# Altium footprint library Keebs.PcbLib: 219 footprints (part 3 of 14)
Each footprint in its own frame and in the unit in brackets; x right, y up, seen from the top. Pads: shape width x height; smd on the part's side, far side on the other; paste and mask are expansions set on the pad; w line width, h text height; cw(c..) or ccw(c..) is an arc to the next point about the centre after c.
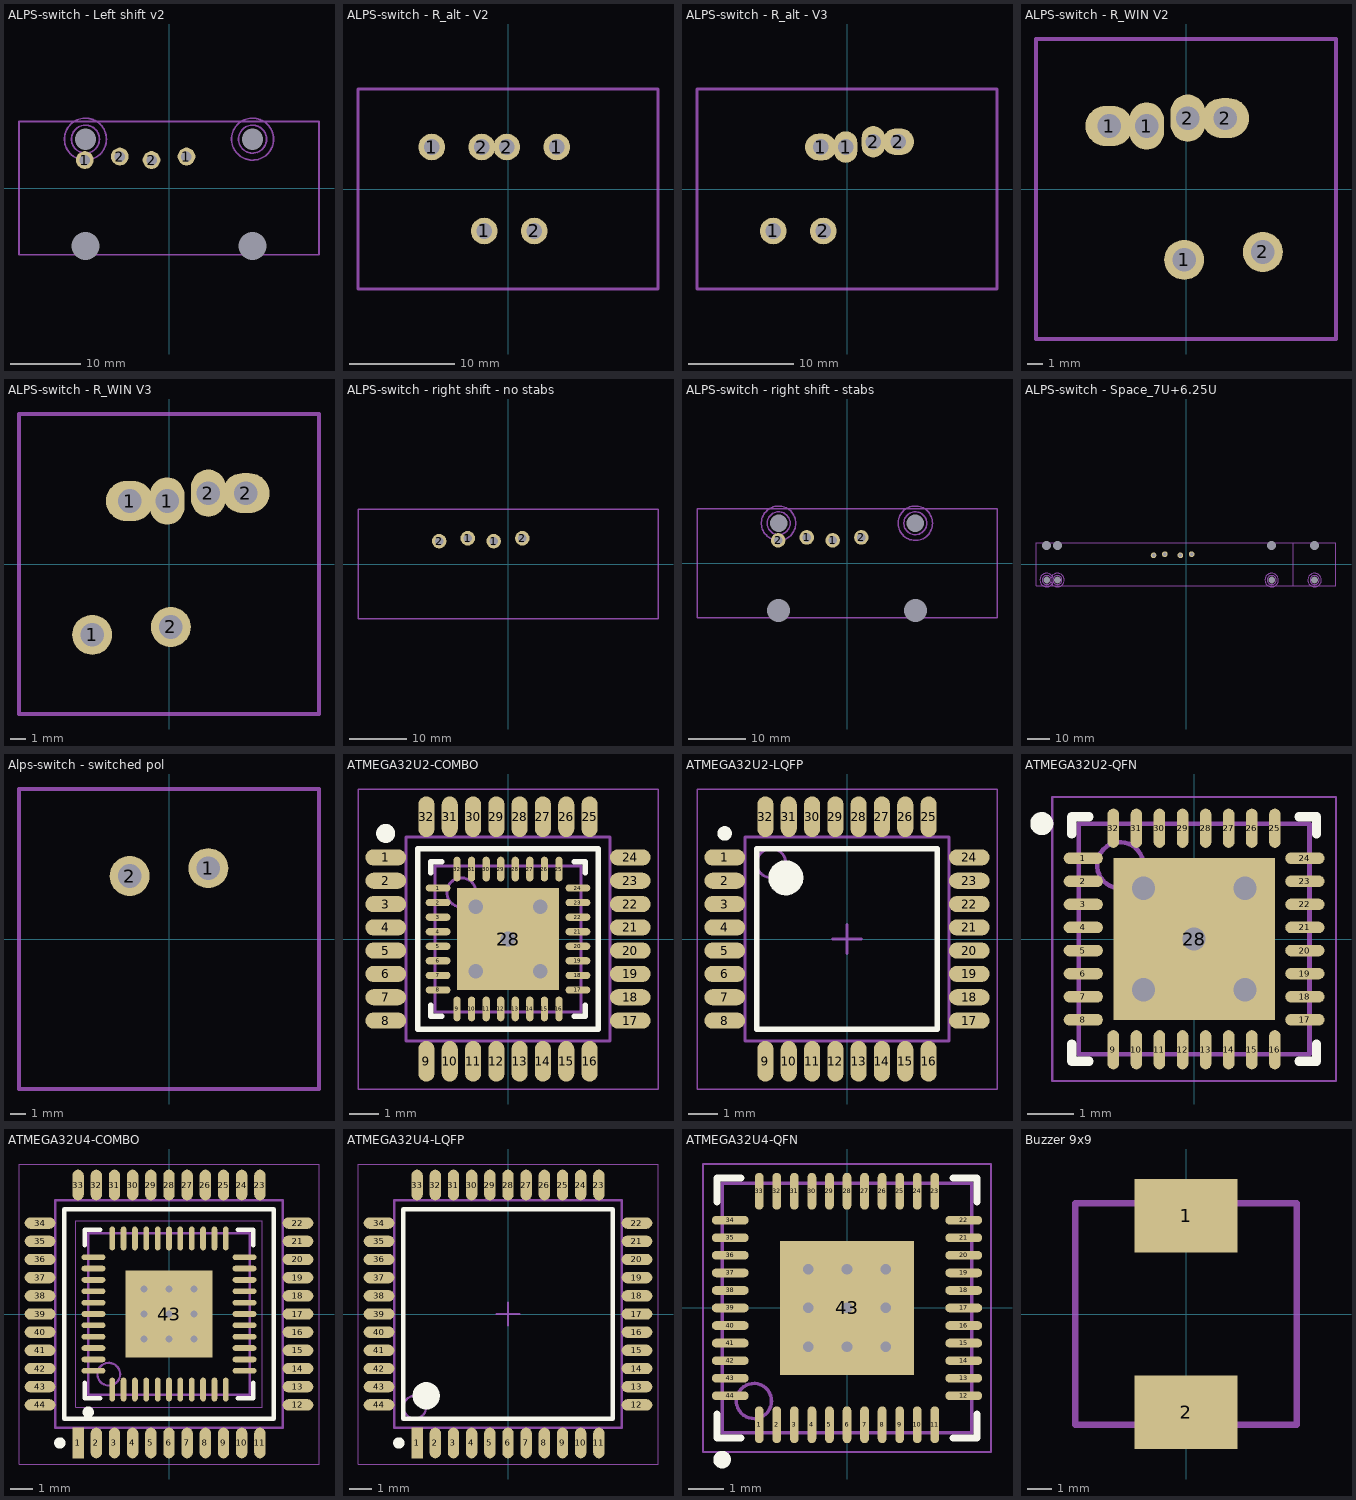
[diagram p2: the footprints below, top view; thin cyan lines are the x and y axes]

## ALPS-switch - Left shift v2 [mm]
pads (10):
  round 2.54 hole 1.5 mask-0.5: 1(-12.025,4) 1(2.5,4.5) 2(-7.025,4.5) 2(-2.5,4)
  round 1.524 hole 4 unplated: ""(-11.938,-8.255) ""(11.938,-8.255)
  round 1.524 hole 3.048 unplated: ""(-11.938,6.985) ""(11.938,6.985)
  round 1 on Mech13: ""(-9.525,0) ""(0,0)
Mechanical 13:
  lines w0.254: -21.431,-9.525 21.431,-9.525 21.431,9.525 -21.431,9.525 -21.431,-9.525
  text ".Designator" at -5.45,-3.925 h0.7
Mechanical 15:
  circle w0.254: c11.938,6.985 r2
  circle w0.254: c11.938,6.985 r3
  circle w0.254: c-11.938,6.985 r2
  circle w0.254: c-11.938,6.985 r3

## ALPS-switch - R_alt - V2 [mm]
pads (9):
  round 2.54 hole 1.5 mask-0.5: 1(-7.263,4) 1(-2.262,-4) 1(4.644,4) 2(-2.5,4) 2(-0.119,4) 2(2.5,-4)
  round 1 on Mech13: ""(-4.763,0) ""(0,0) ""(2.381,0)
Mechanical 13:
  lines w0.254: -14.287,-9.525 -14.287,9.525 14.287,9.525 14.287,-9.525 -14.287,-9.525
  text ".Designator" at -10.775,-6.175 h0.7

## ALPS-switch - R_alt - V3 [mm]
pads (9):
  round 2.54 hole 1.5 mask-0.5: 1(-7.025,-4) 2(-2.262,-4)
  oval 3x2.54 hole 1.5 mask-0.7: 1(-2.5,4) 2(4.881,4.5)
  oval 2.2x3 hole 1.5 mask-0.7: 1(-0.119,4) 2(2.5,4.5)
  round 1 on Mech13: ""(-4.763,0) ""(0,0) ""(2.381,0)
Mechanical 13:
  lines w0.254: -14.287,-9.525 -14.287,9.525 14.287,9.525 14.287,-9.525 -14.287,-9.525
  text ".Designator" at -10.775,-6.175 h0.7

## ALPS-switch - R_WIN V2 [mm]
pads (9):
  oval 3x2.54 hole 1.5 mask-0.7: 1(-4.881,4) 2(2.5,4.5)
  oval 2.2x3 hole 1.5 mask-0.7: 1(-2.5,4) 2(0.119,4.5)
  round 2.54 hole 1.5 mask-0.5: 1(-0.119,-4.5) 2(4.881,-4)
  round 1 on Mech13: ""(-2.381,0) ""(0,0) ""(2.381,0)
Mechanical 13:
  lines w0.254: -9.525,-9.525 9.525,-9.525 9.525,9.525 -9.525,9.525 -9.525,-9.525
  text ".Designator" at -4.225,-8.325 h0.7

## ALPS-switch - R_WIN V3 [mm]
pads (9):
  round 2.54 hole 1.5 mask-0.5: 1(-4.881,-4.5) 2(0.119,-4)
  oval 3x2.54 hole 1.5 mask-0.7: 1(-2.5,4) 2(4.881,4.5)
  oval 2.2x3 hole 1.5 mask-0.7: 1(-0.119,4) 2(2.5,4.5)
  round 1 on Mech13: ""(-2.381,0) ""(0,0) ""(2.381,0)
Mechanical 13:
  lines w0.254: -9.525,-9.525 -9.525,9.525 9.525,9.525 9.525,-9.525 -9.525,-9.525
  text ".Designator" at -4.225,-8.325 h0.7

## ALPS-switch - right shift - no stabs [mm]
pads (6):
  round 2.54 hole 1.5 mask-0.5: 1(-7.025,4.5) 1(-2.5,4) 2(-12.025,4) 2(2.5,4.5)
  round 1 on Mech13: ""(-9.525,0) ""(0,0)
Mechanical 13:
  lines w0.254: -26.194,-9.525 26.194,-9.525 26.194,9.525 -26.194,9.525 -26.194,-9.525
  text ".Designator" at -4.3,-5.55 h0.7

## ALPS-switch - right shift - stabs [mm]
pads (10):
  round 2.54 hole 1.5 mask-0.5: 1(-7.025,4.5) 1(-2.5,4) 2(-12.025,4) 2(2.5,4.5)
  round 1.524 hole 4 unplated: ""(-11.938,-8.255) ""(11.938,-8.255)
  round 1.524 hole 3.048 unplated: ""(-11.938,6.985) ""(11.938,6.985)
  round 1 on Mech13: ""(-9.525,0) ""(0,0)
Mechanical 13:
  lines w0.254: -26.194,-9.525 -26.194,9.525 26.194,9.525 26.194,-9.525 -26.194,-9.525
  text ".Designator" at -4.3,-5.55 h0.7
Mechanical 15:
  circle w0.254: c11.938,6.985 r2
  circle w0.254: c11.938,6.985 r3
  circle w0.254: c-11.938,6.985 r2
  circle w0.254: c-11.938,6.985 r3

## ALPS-switch - Space_7U+6.25U [mm]
pads (14):
  round 2.54 hole 1.5 mask-0.5: 1(-9.406,4.5) 1(-2.5,4) 2(-14.406,4) 2(2.5,4.5)
  round 1.524 hole 3.048 unplated: ""(-61.91,-6.985) ""(-57.15,-6.985) ""(38.09,-6.985) ""(57.15,-6.985)
  round 1.524 hole 4 unplated: ""(-61.91,8.255) ""(-57.15,8.255) ""(38.09,8.255) ""(57.15,8.255)
  round 1 on Mech13: ""(-11.906,0) ""(0,0)
Mechanical 13:
  lines w0.254: 47.621,-9.525 47.621,9.525 ; -66.675,-9.525 66.675,-9.525 66.675,9.525 -66.675,9.525 -66.675,-9.525
  text ".Designator" at 7.625,-2.4 h0.7
Mechanical 15:
  circle w0.254: c-61.91,-6.985 r2
  circle w0.254: c-61.91,-6.985 r3
  circle w0.254: c-57.15,-6.985 r2
  circle w0.254: c-57.15,-6.985 r3
  circle w0.254: c38.09,-6.985 r2
  circle w0.254: c38.09,-6.985 r3
  circle w0.254: c57.15,-6.985 r2
  circle w0.254: c57.15,-6.985 r3
  text "6.25U" at 46.265,-3.6 h1.52
  text "7U" at 65.831,-1.85 h1.52

## Alps-switch - switched pol [mm]
pads (3):
  round 2.54 hole 1.5 mask-0.5: 1(2.5,4.5) 2(-2.5,4)
  round 1 on Mech13: ""(0,0)
Mechanical 13:
  lines w0.254: -9.525,-9.525 9.525,-9.525 9.525,9.525 -9.525,9.525 -9.525,-9.525
  text ".Designator" at -3.575,-3.7 h0.7

## ATMEGA32U2-COMBO [mm]
height 1.6
pads (65):
  oval 1.4x0.55 smd: 1(-4.2,2.8) 2(-4.2,2) 3(-4.2,1.2) 4(-4.2,0.4) 5(-4.2,-0.4) 6(-4.2,-1.2) 7(-4.2,-2) 8(-4.2,-2.8) 17(4.2,-2.8) 18(4.2,-2) 19(4.2,-1.2) 20(4.2,-0.4) 21(4.2,0.4) 22(4.2,1.2) 23(4.2,2) 24(4.2,2.8)
  oval 0.85x0.25 smd: 1(-2.4,1.75) 2(-2.4,1.25) 3(-2.4,0.75) 4(-2.4,0.25) 5(-2.4,-0.25) 6(-2.4,-0.75) 7(-2.4,-1.25) 8(-2.4,-1.75) 17(2.4,-1.75) 18(2.4,-1.25) 19(2.4,-0.75) 20(2.4,-0.25) 21(2.4,0.25) 22(2.4,0.75) 23(2.4,1.25) 24(2.4,1.75)
  oval 0.55x1.4 smd: 9(-2.8,-4.2) 10(-2,-4.2) 11(-1.2,-4.2) 12(-0.4,-4.2) 13(0.4,-4.2) 14(1.2,-4.2) 15(2,-4.2) 16(2.8,-4.2) 25(2.8,4.2) 26(2,4.2) 27(1.2,4.2) 28(0.4,4.2) 29(-0.4,4.2) 30(-1.2,4.2) 31(-2,4.2) 32(-2.8,4.2)
  oval 0.25x0.85 smd: 9(-1.75,-2.4) 10(-1.25,-2.4) 11(-0.75,-2.4) 12(-0.25,-2.4) 13(0.25,-2.4) 14(0.75,-2.4) 15(1.25,-2.4) 16(1.75,-2.4) 25(1.75,2.4) 26(1.25,2.4) 27(0.75,2.4) 28(0.25,2.4) 29(-0.25,2.4) 30(-0.75,2.4) 31(-1.25,2.4) 32(-1.75,2.4)
  rect 3.5x3.5 smd: 28(0,0)
via 1.1,-1.1 diameter 1 hole 0.5
via -1.1,-1.1 diameter 1 hole 0.5
via 0,0 diameter 1 hole 0.5
via 1.1,1.1 diameter 1 hole 0.5
via -1.1,1.1 diameter 1 hole 0.5
Top Overlay:
  circle w0.4: c-4.2,3.625 r0.125
  lines w0.2: -2.65,-2.275 -2.65,-2.65 -2.275,-2.65 ; -2.65,2.275 -2.65,2.65 -2.275,2.65 ; 2.275,-2.65 2.65,-2.65 2.65,-2.275 ; 2.275,2.65 2.65,2.65 2.65,2.275 ; -3.1,-3.1 -3.1,3.1 3.1,3.1 3.1,-3.1 -3.1,-3.1
Mechanical 13:
  circle w0.1: c-1.6,1.6 r0.5
  lines w0.1: -3.5,-3.5 -3.5,3.5 3.5,3.5 3.5,-3.5 -3.5,-3.5 ; -2.5,-2.5 2.5,-2.5 2.5,2.5 -2.5,2.5 -2.5,-2.5
  text ".Designator" at -1.679,-0.15 h0.35
Mechanical 15:
  lines w0.05: -5.15,-5.15 -5.15,5.15 5.15,5.15 5.15,-5.15 -5.15,-5.15 ; -3.075,-3.075 3.075,-3.075 3.075,3.075 -3.075,3.075 -3.075,-3.075
  lines w0.1: -0.5,0 0.5,0 -0.5,0 ; 0,-0.5 0,0.5 0,-0.5
3D body "QFN50P500X500X100_HS-33N.step": height 1, standoff 0, extent -2.51,-2.51 2.51,2.51

## ATMEGA32U2-LQFP [mm]
height 1.6
pads (32):
  oval 1.4x0.55 smd: 1(-4.2,2.8) 2(-4.2,2) 3(-4.2,1.2) 4(-4.2,0.4) 5(-4.2,-0.4) 6(-4.2,-1.2) 7(-4.2,-2) 8(-4.2,-2.8) 17(4.2,-2.8) 18(4.2,-2) 19(4.2,-1.2) 20(4.2,-0.4) 21(4.2,0.4) 22(4.2,1.2) 23(4.2,2) 24(4.2,2.8)
  oval 0.55x1.4 smd: 9(-2.8,-4.2) 10(-2,-4.2) 11(-1.2,-4.2) 12(-0.4,-4.2) 13(0.4,-4.2) 14(1.2,-4.2) 15(2,-4.2) 16(2.8,-4.2) 25(2.8,4.2) 26(2,4.2) 27(1.2,4.2) 28(0.4,4.2) 29(-0.4,4.2) 30(-1.2,4.2) 31(-2,4.2) 32(-2.8,4.2)
Top Overlay:
  circle w0.6: c-2.1,2.1 r0.3
  circle w0.25: c-4.2,3.625 r0.125
  lines w0.2: -3.1,-3.1 3.1,-3.1 3.1,3.1 -3.1,3.1 -3.1,-3.1
Mechanical 13:
  circle w0.1: c-2.6,2.6 r0.5
  lines w0.1: -3.5,-3.5 3.5,-3.5 3.5,3.5 -3.5,3.5 -3.5,-3.5
  text ".Designator" at -1.679,-0.15 h0.35
Mechanical 15:
  lines w0.05: -5.15,-5.15 5.15,-5.15 5.15,5.15 -5.15,5.15 -5.15,-5.15
  lines w0.1: -0.5,0 0.5,0 ; 0,-0.5 0,0.5
3D body "ATMEGA32U2-LQFP.step": height 1.6, standoff 0, extent -4.5,-4.5 4.5,4.5

## ATMEGA32U2-QFN [mm] "QFN, 32-Leads, Body 5,00x5,00mm, Pitch 0,50mm, Thermal Pad 3,60x3,60mm, IPC Medium Density"
height 1
pads (33):
  oval 0.85x0.25 smd: 1(-2.4,1.75) 2(-2.4,1.25) 3(-2.4,0.75) 4(-2.4,0.25) 5(-2.4,-0.25) 6(-2.4,-0.75) 7(-2.4,-1.25) 8(-2.4,-1.75) 17(2.4,-1.75) 18(2.4,-1.25) 19(2.4,-0.75) 20(2.4,-0.25) 21(2.4,0.25) 22(2.4,0.75) 23(2.4,1.25) 24(2.4,1.75)
  oval 0.25x0.85 smd: 9(-1.75,-2.4) 10(-1.25,-2.4) 11(-0.75,-2.4) 12(-0.25,-2.4) 13(0.25,-2.4) 14(0.75,-2.4) 15(1.25,-2.4) 16(1.75,-2.4) 25(1.75,2.4) 26(1.25,2.4) 27(0.75,2.4) 28(0.25,2.4) 29(-0.25,2.4) 30(-0.75,2.4) 31(-1.25,2.4) 32(-1.75,2.4)
  rect 3.5x3.5 smd: 28(0,0)
via 1.1,-1.1 diameter 1 hole 0.5
via -1.1,-1.1 diameter 1 hole 0.5
via 0,0 diameter 1 hole 0.5
via 1.1,1.1 diameter 1 hole 0.5
via -1.1,1.1 diameter 1 hole 0.5
Top Overlay:
  circle w0.25: c-3.3,2.5 r0.125
  lines w0.2: -2.65,-2.275 -2.65,-2.65 -2.275,-2.65 ; -2.65,2.275 -2.65,2.65 -2.275,2.65 ; 2.275,-2.65 2.65,-2.65 2.65,-2.275 ; 2.275,2.65 2.65,2.65 2.65,2.275
Mechanical 13:
  circle w0.1: c-1.6,1.6 r0.5
  lines w0.1: -2.5,-2.5 -2.5,2.5 2.5,2.5 2.5,-2.5 -2.5,-2.5
  text ".Designator" at -1.941,-0.479 h0.35
Mechanical 15:
  lines w0.05: -3.075,-3.075 -3.075,3.075 3.075,3.075 3.075,-3.075 -3.075,-3.075
  lines w0.1: -0.5,0 0.5,0 ; 0,-0.5 0,0.5
3D body "QFN50P500X500X100_HS-33N.step": height 1, standoff 0, extent -2.51,-2.51 2.51,2.51

## ATMEGA32U4-COMBO [mm] "QFP, 44-Leads, Body 9,95x9,95mm, Pitch 0,80mm, IPC Medium Density"
height 2.45
pads (89):
  rect 0.5x1.35 smd: 1(-4,-5.675)
  oval 0.25x1.05 smd: 1(-2.5,-3.325) 2(-2,-3.325) 3(-1.5,-3.325) 4(-1,-3.325) 5(-0.5,-3.325) 6(0,-3.325) 7(0.5,-3.325) 8(1,-3.325) 9(1.5,-3.325) 10(2,-3.325) 11(2.5,-3.325) 23(2.5,3.325) 24(2,3.325) 25(1.5,3.325) 26(1,3.325) 27(0.5,3.325) 28(0,3.325) 29(-0.5,3.325) 30(-1,3.325) 31(-1.5,3.325) 32(-2,3.325) 33(-2.5,3.325)
  oval 0.5x1.35 smd: 2(-3.2,-5.675) 3(-2.4,-5.675) 4(-1.6,-5.675) 5(-0.8,-5.675) 6(0,-5.675) 7(0.8,-5.675) 8(1.6,-5.675) 9(2.4,-5.675) 10(3.2,-5.675) 11(4,-5.675) 23(4,5.675) 24(3.2,5.675) 25(2.4,5.675) 26(1.6,5.675) 27(0.8,5.675) 28(0,5.675) 29(-0.8,5.675) 30(-1.6,5.675) 31(-2.4,5.675) 32(-3.2,5.675) 33(-4,5.675)
  oval 1.05x0.25 smd: 12(3.325,-2.5) 13(3.325,-2) 14(3.325,-1.5) 15(3.325,-1) 16(3.325,-0.5) 17(3.325,0) 18(3.325,0.5) 19(3.325,1) 20(3.325,1.5) 21(3.325,2) 22(3.325,2.5) 34(-3.325,2.5) 35(-3.325,2) 36(-3.325,1.5) 37(-3.325,1) 38(-3.325,0.5) 39(-3.325,0) 40(-3.325,-0.5) 41(-3.325,-1) 42(-3.325,-1.5) 43(-3.325,-2) 44(-3.325,-2.5)
  oval 1.35x0.5 smd: 12(5.675,-4) 13(5.675,-3.2) 14(5.675,-2.4) 15(5.675,-1.6) 16(5.675,-0.8) 17(5.675,0) 18(5.675,0.8) 19(5.675,1.6) 20(5.675,2.4) 21(5.675,3.2) 22(5.675,4) 34(-5.675,4) 35(-5.675,3.2) 36(-5.675,2.4) 37(-5.675,1.6) 38(-5.675,0.8) 39(-5.675,0) 40(-5.675,-0.8) 41(-5.675,-1.6) 42(-5.675,-2.4) 43(-5.675,-3.2) 44(-5.675,-4)
  rect 3.81x3.81 smd paste-1000: 43(0,0)
via -1.1,-1.1 diameter 0.6 hole 0.3
via -1.1,0 diameter 0.6 hole 0.3
via -1.1,1.1 diameter 0.6 hole 0.3
via 0,-1.1 diameter 0.6 hole 0.3
via 0,0 diameter 0.6 hole 0.3
via 0,1.1 diameter 0.6 hole 0.3
via 1.1,-1.1 diameter 0.6 hole 0.3
via 1.1,0 diameter 0.6 hole 0.3
via 1.1,1.1 diameter 0.6 hole 0.3
Top Overlay:
  circle w0.25: c-3.556,-4.318 r0.125
  circle w0.25: c-4.8,-5.675 r0.125
  lines w0.2: -3.7,-3.025 -3.7,-3.7 -3.025,-3.7 ; -3.7,3.025 -3.7,3.7 -3.025,3.7 ; 3.025,-3.7 3.7,-3.7 3.7,-3.025 ; 3.025,3.7 3.7,3.7 3.7,3.025 ; -4.6,-4.6 -4.6,4.6 4.6,4.6 4.6,-4.6 -4.6,-4.6
Top Paste:
  rectangle: -1.778,-1.778 -0.254,-0.254
  region: -1.778,1.778 -1.778,0.254 -0.254,0.254 -0.254,1.778
  region: 1.778,1.778 0.254,1.778 0.254,0.254 1.778,0.254
  region: 1.778,-1.778 1.778,-0.254 0.254,-0.254 0.254,-1.778
Mechanical 13:
  circle w0.1: c-2.65,-2.65 r0.5
  lines w0.1: -5,-5 -5,5 5,5 5,-5 -5,-5 ; -3.55,-3.55 3.55,-3.55 3.55,3.55 -3.55,3.55 -3.55,-3.55
  text ".Designator" at 0.152,-2.345 h0.5
Mechanical 15:
  lines w0.05: -6.6,-6.6 -6.6,6.6 6.6,6.6 6.6,-6.6 -6.6,-6.6 ; -4.1,-4.1 4.1,-4.1 4.1,4.1 -4.1,4.1 -4.1,-4.1
  lines w0.1: -0.5,0 0.5,0 -0.5,0 ; 0,-0.5 0,0.5 0,-0.5
3D body "ATMEGA32U4-combo.step": height 1, standoff 0, extent -3.6,-3.6 3.6,3.6

## ATMEGA32U4-LQFP [mm] "QFP, 44-Leads, Body 9,95x9,95mm, Pitch 0,80mm, IPC Medium Density"
height 2.45
pads (44):
  rect 0.5x1.35 smd: 1(-4,-5.675)
  oval 0.5x1.35 smd: 2(-3.2,-5.675) 3(-2.4,-5.675) 4(-1.6,-5.675) 5(-0.8,-5.675) 6(0,-5.675) 7(0.8,-5.675) 8(1.6,-5.675) 9(2.4,-5.675) 10(3.2,-5.675) 11(4,-5.675) 23(4,5.675) 24(3.2,5.675) 25(2.4,5.675) 26(1.6,5.675) 27(0.8,5.675) 28(0,5.675) 29(-0.8,5.675) 30(-1.6,5.675) 31(-2.4,5.675) 32(-3.2,5.675) 33(-4,5.675)
  oval 1.35x0.5 smd: 12(5.675,-4) 13(5.675,-3.2) 14(5.675,-2.4) 15(5.675,-1.6) 16(5.675,-0.8) 17(5.675,0) 18(5.675,0.8) 19(5.675,1.6) 20(5.675,2.4) 21(5.675,3.2) 22(5.675,4) 34(-5.675,4) 35(-5.675,3.2) 36(-5.675,2.4) 37(-5.675,1.6) 38(-5.675,0.8) 39(-5.675,0) 40(-5.675,-0.8) 41(-5.675,-1.6) 42(-5.675,-2.4) 43(-5.675,-3.2) 44(-5.675,-4)
Top Overlay:
  circle w0.6: c-3.6,-3.6 r0.3
  circle w0.25: c-4.8,-5.675 r0.125
  lines w0.2: -4.6,-4.6 -4.6,4.6 4.6,4.6 4.6,-4.6 -4.6,-4.6
Mechanical 13:
  circle w0.1: c-4.1,-4.1 r0.5
  lines w0.1: -5,-5 -5,5 5,5 5,-5 -5,-5
  text ".Designator" at 0.15,-1.425 h0.35
Mechanical 15:
  lines w0.05: -6.6,-6.6 -6.6,6.6 6.6,6.6 6.6,-6.6 -6.6,-6.6
  lines w0.1: -0.5,0 0.5,0 ; 0,-0.5 0,0.5
3D body "tqfp-44.STEP": height 1, standoff -0.11, extent -6,-6 6,6

## ATMEGA32U4-QFN [mm]
height 1
pads (45):
  oval 0.25x1.05 smd: 1(-2.5,-3.325) 2(-2,-3.325) 3(-1.5,-3.325) 4(-1,-3.325) 5(-0.5,-3.325) 6(0,-3.325) 7(0.5,-3.325) 8(1,-3.325) 9(1.5,-3.325) 10(2,-3.325) 11(2.5,-3.325) 23(2.5,3.325) 24(2,3.325) 25(1.5,3.325) 26(1,3.325) 27(0.5,3.325) 28(0,3.325) 29(-0.5,3.325) 30(-1,3.325) 31(-1.5,3.325) 32(-2,3.325) 33(-2.5,3.325)
  oval 1.05x0.25 smd: 12(3.325,-2.5) 13(3.325,-2) 14(3.325,-1.5) 15(3.325,-1) 16(3.325,-0.5) 17(3.325,0) 18(3.325,0.5) 19(3.325,1) 20(3.325,1.5) 21(3.325,2) 22(3.325,2.5) 34(-3.325,2.5) 35(-3.325,2) 36(-3.325,1.5) 37(-3.325,1) 38(-3.325,0.5) 39(-3.325,0) 40(-3.325,-0.5) 41(-3.325,-1) 42(-3.325,-1.5) 43(-3.325,-2) 44(-3.325,-2.5)
  rect 3.81x3.81 smd paste-1000: 43(0,0)
via 1.1,1.1 diameter 0.6 hole 0.3
via 1.1,0 diameter 0.6 hole 0.3
via 1.1,-1.1 diameter 0.6 hole 0.3
via 0,1.1 diameter 0.6 hole 0.3
via 0,0 diameter 0.6 hole 0.3
via 0,-1.1 diameter 0.6 hole 0.3
via -1.1,1.1 diameter 0.6 hole 0.3
via -1.1,0 diameter 0.6 hole 0.3
via -1.1,-1.1 diameter 0.6 hole 0.3
Top Overlay:
  circle w0.25: c-3.556,-4.318 r0.125
  lines w0.2: -3.7,-3.025 -3.7,-3.7 -3.025,-3.7 ; -3.7,3.025 -3.7,3.7 -3.025,3.7 ; 3.025,-3.7 3.7,-3.7 3.7,-3.025 ; 3.025,3.7 3.7,3.7 3.7,3.025
Top Paste:
  region: 1.778,-1.778 1.778,-0.254 0.254,-0.254 0.254,-1.778
  region: 1.778,1.778 0.254,1.778 0.254,0.254 1.778,0.254
  region: -1.778,1.778 -1.778,0.254 -0.254,0.254 -0.254,1.778
  rectangle: -1.778,-1.778 -0.254,-0.254
Mechanical 13:
  circle w0.1: c-2.65,-2.65 r0.5
  lines w0.1: -3.55,-3.55 -3.55,3.55 3.55,3.55 3.55,-3.55 -3.55,-3.55
  text ".Designator" at 0.152,-2.345 h0.5
Mechanical 15:
  lines w0.05: -4.1,-4.1 -4.1,4.1 4.1,4.1 4.1,-4.1 -4.1,-4.1
  lines w0.1: -0.5,0 0.5,0 ; 0,-0.5 0,0.5
3D body "ATMEGA32U4-combo.step": height 1, standoff 0, extent -3.6,-3.6 3.6,3.6

## Buzzer 9x9 [mm]
pads (2):
  rect 4.2x3 smd: 1(0,4) 2(0,-4)
Mechanical 13:
  lines w0.254: -4.5,-4.5 4.5,-4.5 4.5,4.5 -4.5,4.5 -4.5,-4.5
  text ".Designator" at -1.917,-0.015 h0.5
3D body "CUI_CPT-9019S-SMT.step": height 1.91, standoff 0, extent -4.551,-4.643 4.449,4.597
